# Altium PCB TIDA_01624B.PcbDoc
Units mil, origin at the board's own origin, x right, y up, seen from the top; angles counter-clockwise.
Board outline 1500.72 x 1500.72 mil, 2 copper layers (Top Layer, Bottom Layer), stack 9.4 mil thick; 37 components, 24 nets, 117 pads, 36 vias.
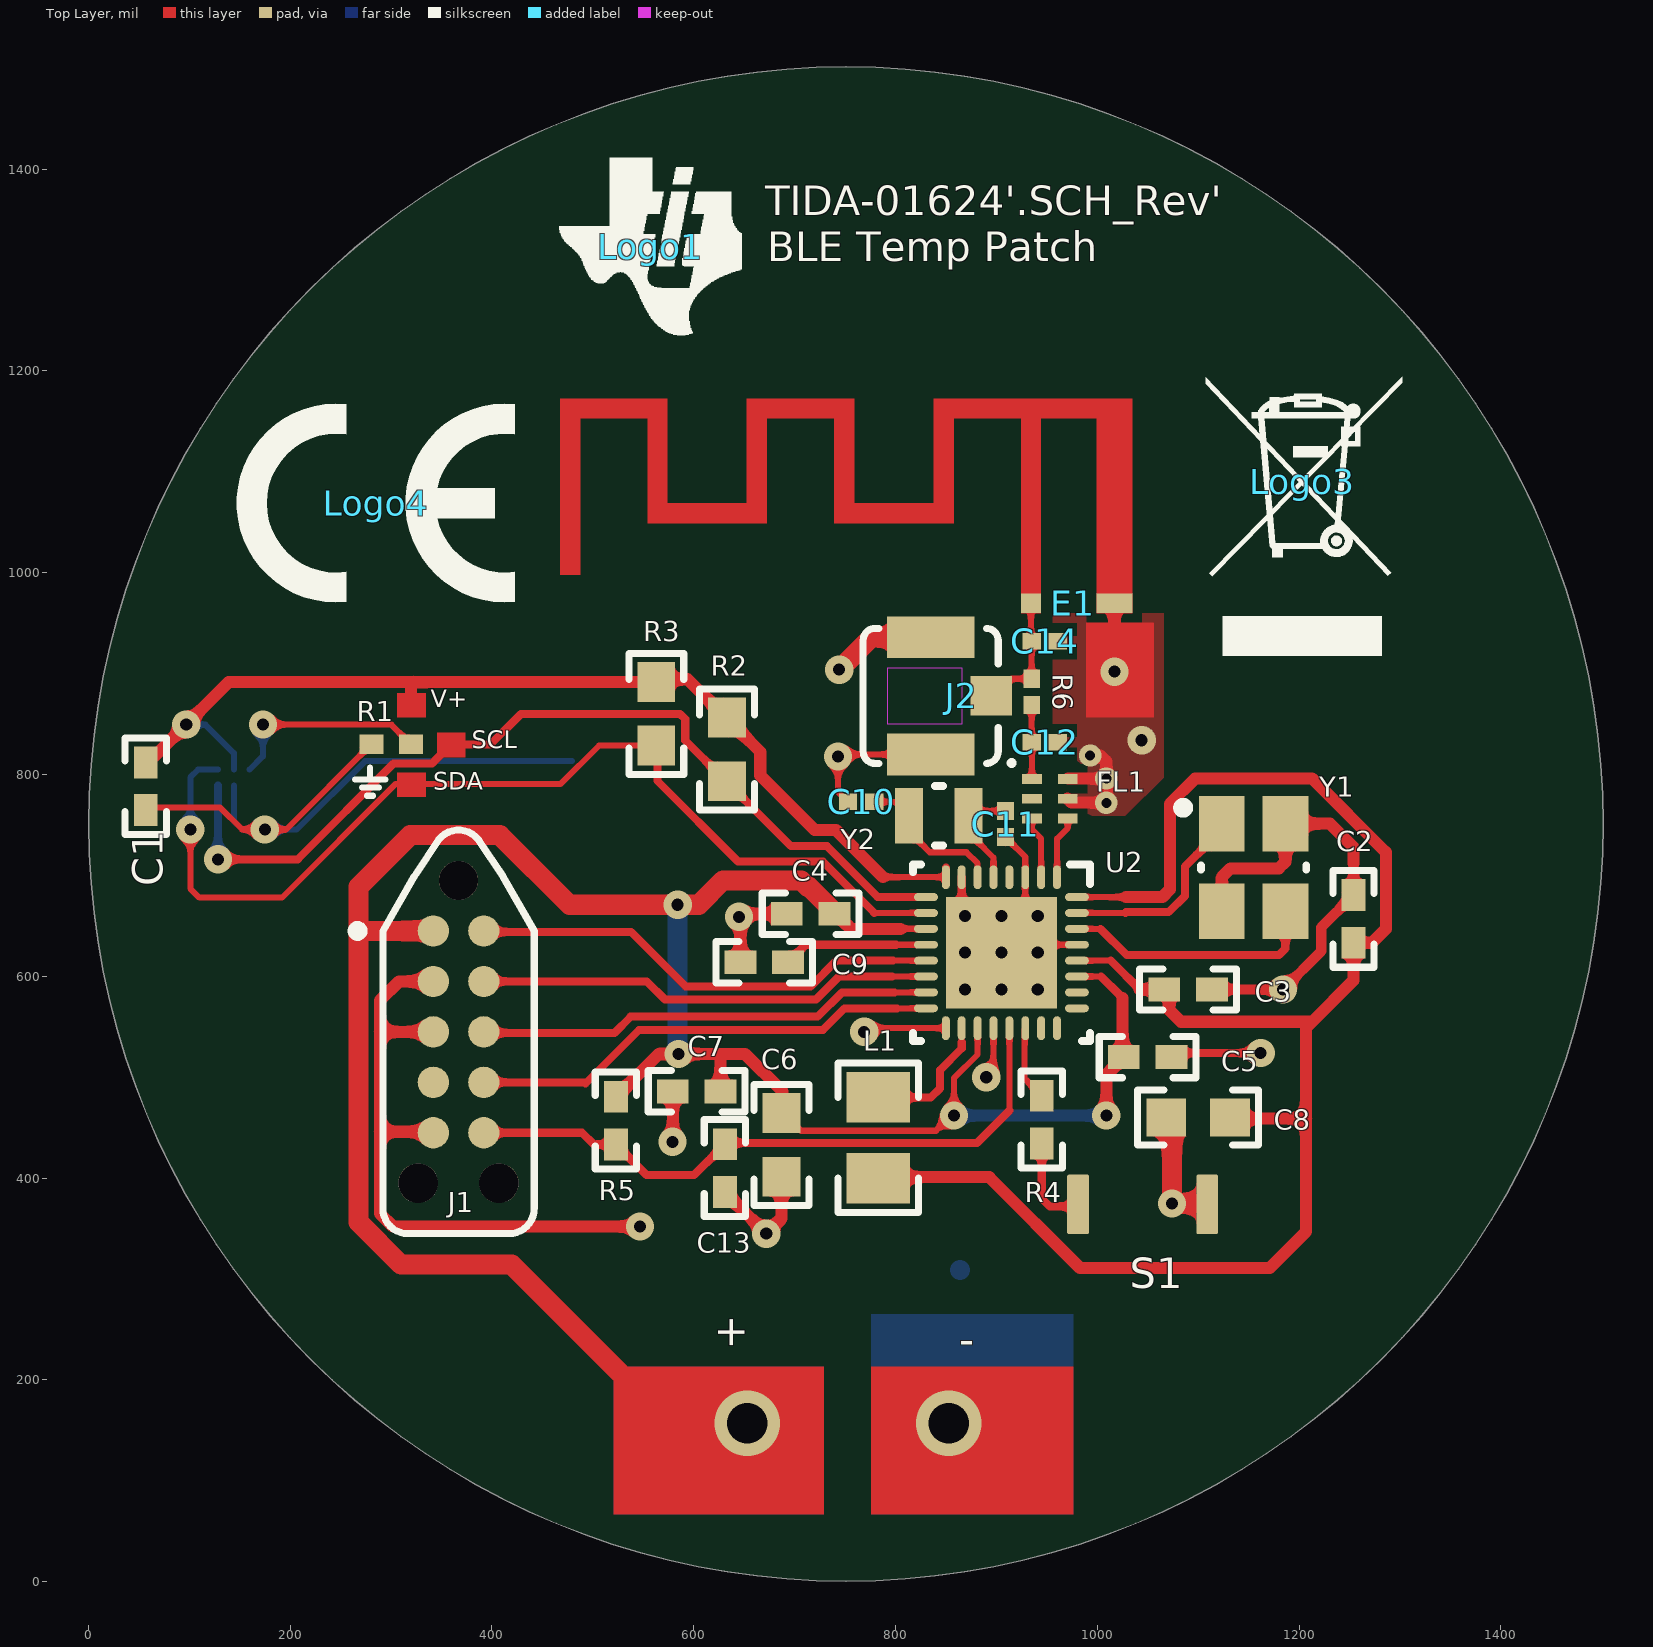
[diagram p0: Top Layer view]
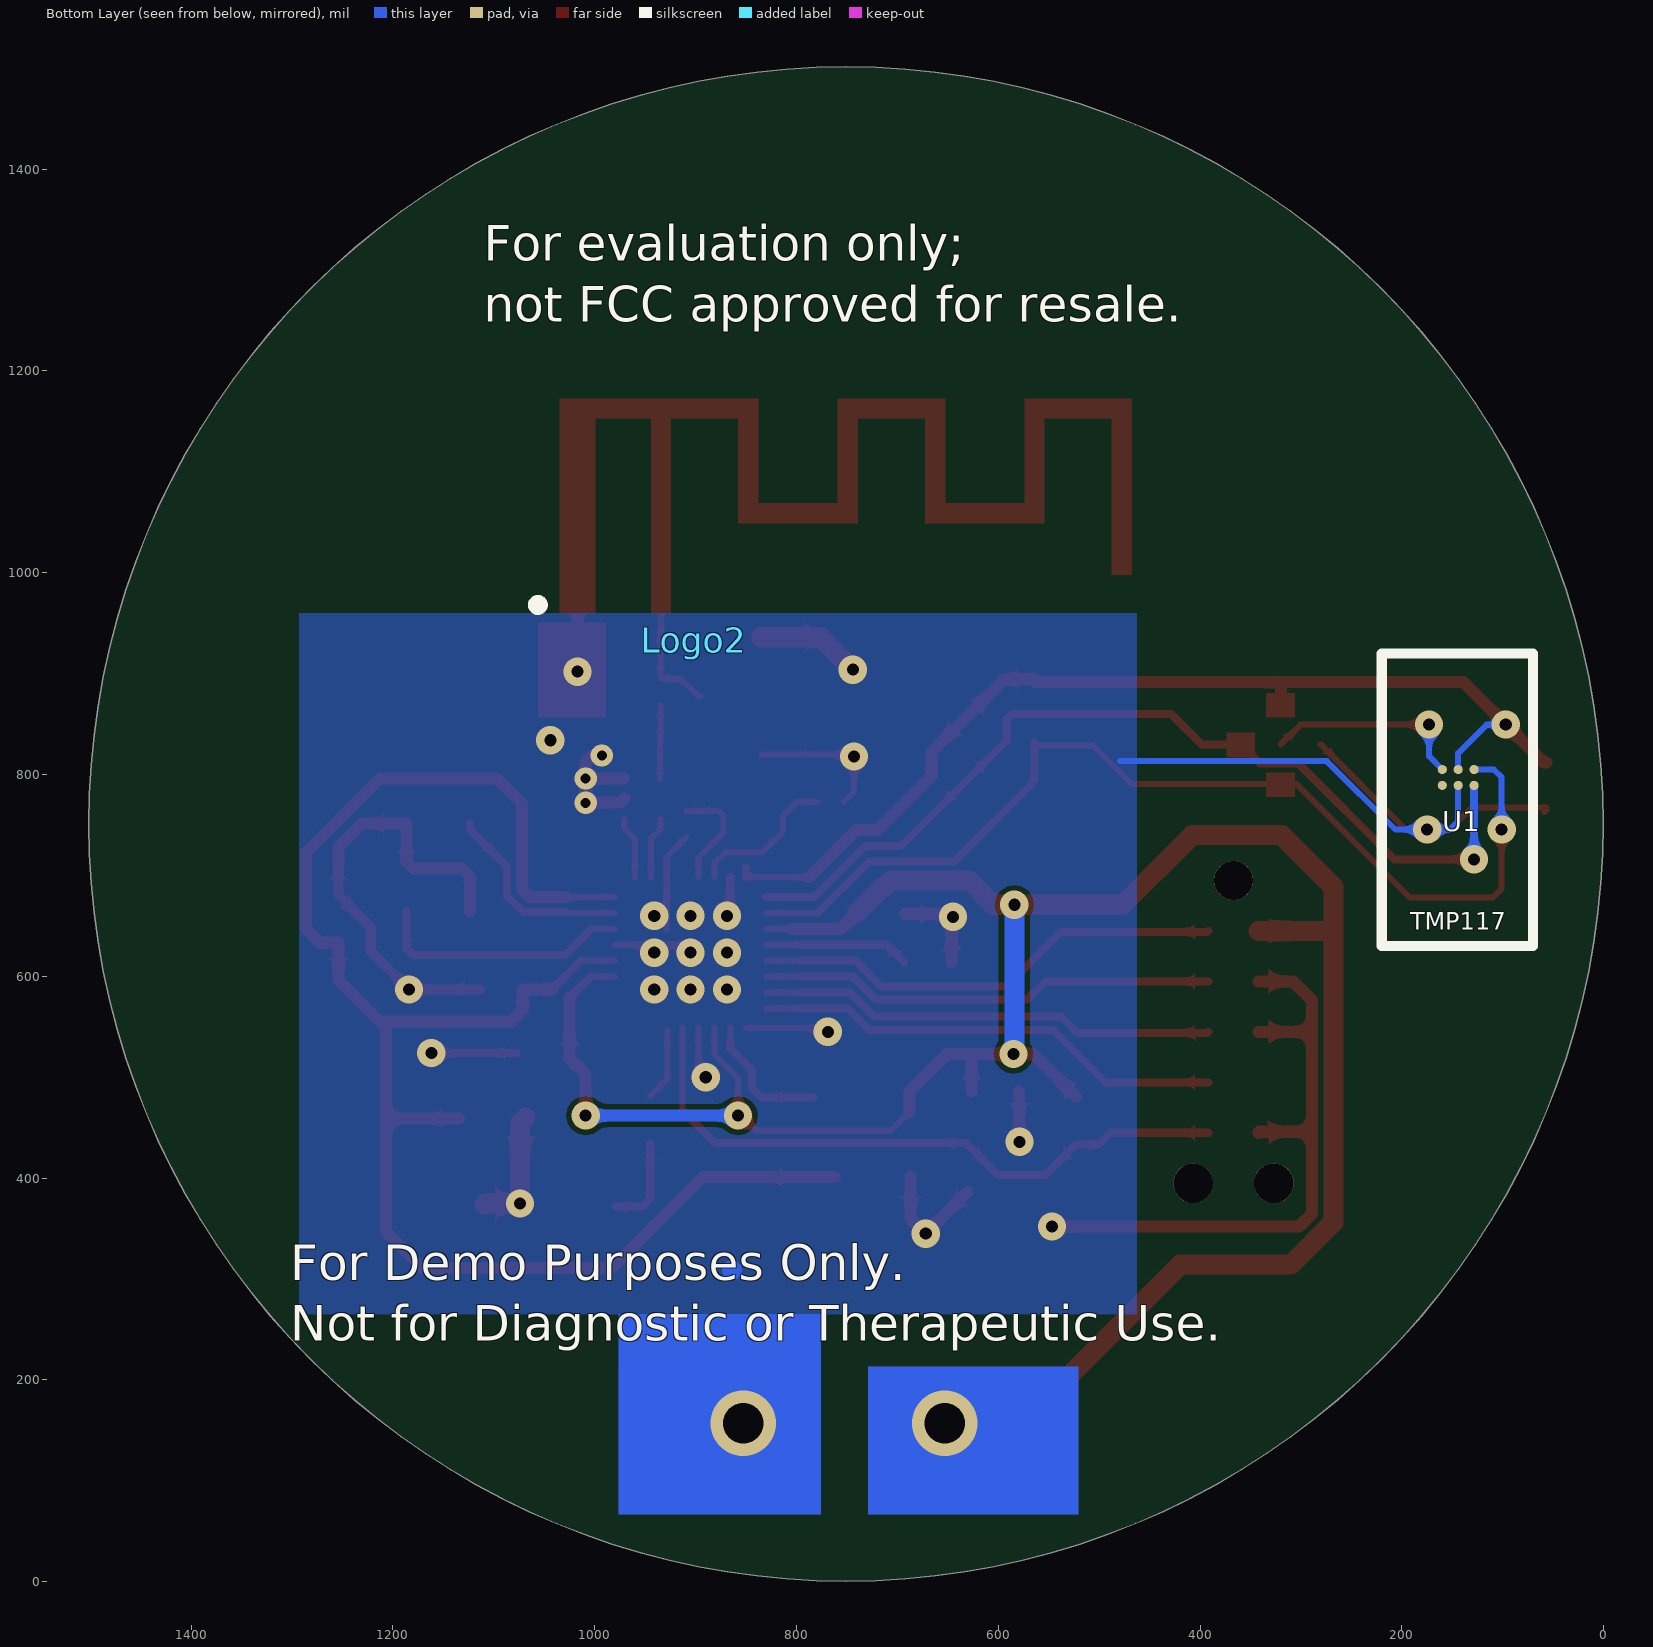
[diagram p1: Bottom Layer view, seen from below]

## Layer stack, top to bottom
Top Solder: solder mask 1, Polymide, Dk 3.3
Top Layer: signal copper 0.7
Stiffener: dielectric 5, Polyimide, Dk 4.2
Flex Substrate: core 3, Polymide, Dk 3.3
Bottom Layer: signal copper 0.7
Bottom Solder: solder mask 1, Polyimide, Dk 3.3

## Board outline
751,0.64 cw(c751,751) 0.64,751 cw(c751,751) 751,1501.36 cw(c751,751) 1501.36,751 cw(c751,751)
board region "Layer Stack Region 1": 220,920 19.55,920 19.85,921.48 32.56,968.94 48.36,1015.46 67.16,1060.85 88.89,1104.91 113.45,1147.45 140.74,1188.3 170.65,1227.28 203.04,1264.22 220,1281.17
board region "Layer Stack Region 1": 220,629.99 10.09,629.99 3.85,677.41 0.64,726.44 0.64,751 0.64,775.56 3.85,824.59 10.26,873.3 19.55,920 220,920
board region "Layer Stack Region 1": 220,220.83 203.04,237.78 170.65,274.72 140.74,313.7 113.45,354.55 88.89,397.09 67.16,441.15 48.36,486.54 32.56,533.06 19.85,580.52 10.26,628.7 10.09,629.99 220,629.99
board region "Layer Stack Region 1": 220,1281.17 237.78,1298.96 274.72,1331.35 313.7,1361.26 354.55,1388.55 397.09,1413.11 441.15,1434.84 486.54,1453.64 533.06,1469.44 580.52,1482.15 628.7,1491.74 677.41,1498.15 726.44,1501.36 751,1501.36 775.56,1501.36 824.59,1498.15 873.3,1491.74 921.48,1482.15 968.94,1469.44 1015.46,1453.64 1060.85,1434.84 1104.91,1413.11 1147.45,1388.55 1188.3,1361.26 1227.28,1331.35 1264.22,1298.96 1298.96,1264.22 1331.35,1227.28 1361.26,1188.3 1388.55,1147.45 1413.11,1104.91 1434.84,1060.85 1453.64,1015.46 1469.44,968.94 1482.15,921.48 1482.45,920 220,920
board region "Layer Stack Region 1": 220,920 1482.45,920 1491.74,873.3 1498.15,824.59 1501.36,775.56 1501.36,751 1501.36,726.44 1498.15,677.41 1491.91,630 220,629.99
board region "Layer Stack Region 1": 220,629.99 1491.91,630 1491.74,628.7 1482.15,580.52 1469.44,533.06 1453.64,486.54 1434.84,441.15 1413.11,397.09 1388.55,354.55 1361.26,313.7 1331.35,274.72 1298.96,237.78 1264.22,203.04 1227.28,170.65 1188.3,140.74 1147.45,113.45 1104.91,88.89 1060.85,67.16 1015.46,48.36 968.94,32.56 921.48,19.85 873.3,10.26 824.59,3.85 775.56,0.64 751,0.64 726.44,0.64 677.41,3.85 628.7,10.26 580.52,19.85 533.06,32.56 486.54,48.36 441.15,67.16 397.09,88.89 354.55,113.45 313.7,140.74 274.72,170.65 237.78,203.04 220,220.83

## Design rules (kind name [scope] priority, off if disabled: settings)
AcuteAngle [All] p1: minimum=4.50000000000000E+0001 checktracksonly=FALSE
AssemblyTestPointUsage [All] p1: valid=2
BoardOutlineClearance BoardOutlineClearance_MountingHoles [OnCopper and InComponentClass('Mounting Holes')] p1 off: gap=40 ignorepadtopadclearanceinfootprint=FALSE
BoardOutlineClearance BoardOutlineClearance_Poly [OnCopper and IsPoly] p2: gap=25 ignorepadtopadclearanceinfootprint=FALSE
BoardOutlineClearance [OnCopper and Not InComponentClass('Logo') and not InComponentClass('FiducialMark') and not InRegion(1000,500,4000,800) and not InPoly] p3 off: gap=40 ignorepadtopadclearanceinfootprint=FALSE
Clearance Clearance_2 [InNamedPolygon('GND_L01_P002') vs InComponent('E1')] p1: gap=0 ignorepadtopadclearanceinfootprint=FALSE
Clearance Clearance_Keepouts [((IsTrack Or IsArc) And Not InPoly) And IsFree and IsKeepOut vs ((IsTrack Or IsArc) And Not InPoly) And IsFree and IsKeepOut] p2: gap=0 ignorepadtopadclearanceinfootprint=FALSE
Clearance Clearance_Poly [InPolygon] p3 off: gap=25 ignorepadtopadclearanceinfootprint=FALSE except(0: Arc-Hole Track-Hole SMDPad-Hole THPad-Hole Via-Hole Fill-Hole Poly-Hole Region-Hole Text-Hole)
Clearance [All] p4: gap=5 ignorepadtopadclearanceinfootprint=FALSE
ComponentClearance ComponentClearance_MountingHoles_FiducialMarks [InComponentClass('Mounting Holes') vs InComponentClass('FiducialMark')] p1: gap=50 collisioncheckmode=3 verticalgap=10 showdistances=FALSE
ComponentClearance ComponentClearance_Shunt [InComponentClass('Header') vs InComponentClass('Shunt')] p2: gap=0 collisioncheckmode=3 verticalgap=0 showdistances=FALSE
ComponentClearance ComponentClearance_Logo [InComponentClass('Logo')] p3: gap=0 collisioncheckmode=3 verticalgap=0 showdistances=FALSE
ComponentClearance ComponentClearance_ScrewToNut [(HasFootprint('NY PMS 440 0025 PH')) vs (HasFootprint('Keystone_1902C'))] p4: gap=5 collisioncheckmode=3 verticalgap=10 showdistances=FALSE
ComponentClearance ComponentClearance_MountingHoles [InComponentClass('Mounting Holes')] p5: gap=250 collisioncheckmode=3 verticalgap=100000 showdistances=FALSE
ComponentClearance ComponentClearance_SmallPassives [HasFootprint('0201*') or HasFootprint('0402*') or HasFootprint('0508') or HasFootprint('0603*') or HasFootprint('0612') or HasFootprint('0805*') or HasFootprint('0815*') or HasFootprint('0830*') or HasFootprint('1206*') or HasFootprint('1210*') or HasFootprint('1808*') or HasFootprint('1812*') or HasFootprint('1825*') or HasFootprint('2010*') or HasFootprint('2220*') or HasFootprint('2225*') or HasFootprint('2512*') or HasFootprint('2728*') or HasFootprint('3518*') vs HasFootprint('0201*') or HasFootprint('0402*') or HasFootprint('0508') or HasFootprint('0603*') or HasFootprint('0612') or HasFootprint('0805*') or HasFootprint('0815*') or HasFootprint('0830*') or HasFootprint('1206*') or HasFootprint('1210*') or HasFootprint('1808*') or HasFootprint('1812*') or HasFootprint('1825*') or HasFootprint('2010*') or HasFootprint('2220*') or HasFootprint('2225*') or HasFootprint('2512*') or HasFootprint('2728*') or HasFootprint('3518*')] p6: gap=14.96 collisioncheckmode=3 verticalgap=10 showdistances=FALSE
ComponentClearance ComponentClearance_THtoSMT [IsThruComponent vs IsSMTComponent] p7: gap=40 collisioncheckmode=3 verticalgap=30 showdistances=FALSE
ComponentClearance ComponentClearance_THtoTH [IsThruComponent vs IsThruComponent] p8: gap=15 collisioncheckmode=3 verticalgap=30 showdistances=FALSE
ComponentClearance [All] p9: gap=15 collisioncheckmode=3 verticalgap=10 showdistances=FALSE
DiffPairsRouting [All] p1: maxlimit=100 minlimit=10 mostfreqgap=10 toplayer_minwidth=15 toplayer_maxwidth=15 toplayer_prefwidth=15 bottomlayer_minwidth=15 bottomlayer_maxwidth=15 bottomlayer_prefwidth=15 maxuncoupledlength=1000
FabricationTestPointUsage TestPointUsage [All] p1: valid=2 allowmultiple=FALSE
FabricationTestpoint Testpoint [All] p1: side=3 testpointundercomponent=TRUE minsize=40 maxsize=100 preferedsize=60 minholesize=0 maxholesize=40 preferedholesize=32 testpointgrid=1 allowsidetop=TRUE allowsidebottom=TRUE usegrid=TRUE gridtolerance=0.01
FanoutControl Fanout_LCC [IsLCC] p1: bgadir=Out bgaviamode=Centered fanoutstyle=Auto fanoutdirection=Alternating viagrid=1 // Fanout_LCC (Default Rule)
FanoutControl Fanout_BGA [IsBGA] p2: bgadir=Out bgaviamode=Centered fanoutstyle=Auto fanoutdirection=Alternating viagrid=1 // Fanout_BGA (Default Rule)
FanoutControl Fanout_Default [All] p4: bgadir=Out bgaviamode=Centered fanoutstyle=Auto fanoutdirection=Alternating viagrid=1 // Fanout_Default (Default Rule)
FanoutControl Fanout_Small [(CompPinCount < 5)] p5: bgadir=Out bgaviamode=Centered fanoutstyle=Auto fanoutdirection=OutThenIn viagrid=1 // Fanout_Small (Default Rule)
HoleSize [All] p1: absolutevalues=TRUE maxlimit=251 minlimit=7.87 maxpercent=80.000 minpercent=20.000
MinimumAnnularRing MinimumAnnularRing_ThermalPadVias [IsVia and InAnyComponent] p1: minimumring=5.91
MinimumAnnularRing [All] p2: minimumring=5
MinimumSolderMaskSliver MinimumSolderMaskSliver_Logo [InComponentClass('Logo') vs InComponentClass('Logo')] p1: minsoldermaskwidth=0.7
MinimumSolderMaskSliver [All] p2: minsoldermaskwidth=2
PlaneConnect [All] p1: planeconnectstyle=Relief reliefexpansion=10 reliefentries=4 reliefconductorwidth=10 reliefairgap=10
PolygonConnect [All] p1: thpad.connectstyle=Relief thpad.reliefconductorwidth=10 thpad.reliefentries=4 thpad.polygonreliefangle="90 Angle" thpad.airgapwidth=10 smdpad.connectstyle=Relief smdpad.reliefconductorwidth=10 smdpad.reliefentries=4 smdpad.polygonreliefangle="90 Angle" smdpad.airgapwidth=10 via.connectstyle=Direct via.reliefconductorwidth=10 via.reliefentries=4 via.polygonreliefangle="90 Angle" via.airgapwidth=10
RoutingVias ThermalPadVias [IsVia and InAnyComponent] p1: holewidth=7.87 width=19.68 viastyle="Through Hole" minholewidth=7.87 minwidth=19.68 maxholewidth=12.99 maxwidth=23.62
RoutingVias [All] p2: holewidth=12 width=28 viastyle="Through Hole" minholewidth=7.9 minwidth=21.9 maxholewidth=40 maxwidth=65
ShortCircuit NoNet [IsComponentVia and not InAnyNet vs IsComponentPad and not InAnyNet] p1: allowed=TRUE
ShortCircuit [All] p2: allowed=FALSE
SilkToBoardRegionClearance [Not ((IsComment or IsDesignator) And (Hide <> 'False')) and not InRegion(1000,500,4000,800)] p1:
SilkToSilkClearance SilkToSilkClearance_Pb-FreeLogo [HasFootprint('FCC_disclaimer') vs HasFootprint('TI_Symbol_Overlay_Small')] p1: silktosilkclearance=0
SilkToSilkClearance SilkToSilkClearance_Pb-FreeLogo_1 [(HasFootprint('Pb-Free_Overlay_Medium') OR HasFootprint('Pb-Free_Overlay_Small')) vs (HasFootprint('Pb-Free_Overlay_Medium') OR HasFootprint('Pb-Free_Overlay_Small'))] p2: silktosilkclearance=0
SilkToSilkClearance [All] p3: silktosilkclearance=4
SilkToSolderMaskClearance "Silk to Solder Mask Opening" [All] p1: minsilkscreentomaskgap=1.5 clearancetoexposedcopper=FALSE
SolderMaskExpansion [All] p1: expansion=1.97
Width [All] p1: maxlimit=20 minlimit=4 preferedwidth=8 checkconnectedcopper=TRUE
14 further rules are at their usual default settings.

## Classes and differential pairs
component class AssemblyNote: ZZ1 ZZ2 ZZ3
component class Logo: Logo1

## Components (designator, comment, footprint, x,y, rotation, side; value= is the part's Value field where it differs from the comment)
C1 "GRM155R71E104KE14D" 0402 57,788.38 r270 top value=0.1uF
C2 "GRM155R71E104KE14D" 0402 1254,657 r270 top value=0.1uF
C3 "GRM155R71E104KE14D" 0402 1090,587 r180 top value=0.1uF
C4 "GRM155R71E104KE14D" 0402 716,662 r0 top value=0.1uF
C5 "GRM155R71E104KE14D" 0402 1050,520 r180 top value=0.1uF
C6 "C1608X5R1E106M080AC" 0603 687,433 r270 top value=10uF
C7 "GRM155R71E104KE14D" 0402 603,486 r180 top value=0.1uF
C8 "C1608X5R1E106M080AC" 0603 1100,460 r180 top value=10uF
C9 "GRM152R60J105ME15D" 0402 670,614 r0 top value=1uF
C10 "Capacitor" 0201 766,773 r180 top value=12pF
C11 "Capacitor" 0201 909,751 r270 top value=12pF
C12 "DNP" 0201_033 948,832 r0 top
C13 "GRM155R71E104KE14D" 0402 631,410 r270 top value=0.1uF
C14 "DNP" 0201_033 948,932 r0 top
E1 "ANTENNA_IIFA" ANTENNA_IIFA 1017,960 r180 top net-tie
FL1 "2450BM14G0011" Johanson_2450BM14G0011 953,776 r0 top
J1 "DNP - Nothing to buy or mount" Tag_TC2050-NL 367,545 r0 top
J2 "U.FL-R-SMT-1(01)" CONN_UFL-R-SMT-1 834.96,878 r180 top
L1 "CKS2125100M-T" 0805_HV 783,440 r270 top value=10uH
Logo1 "Texas Instruments" TI_Symbol_Overlay_Small 557,1323 r0 top
Logo2 "FCC disclaimer" FCC_disclaimer 901.89,933.12 r180 bottom
Logo3 "WEEE logo" WEEE_Minimum 1203,1090 r0 top
Logo4 "CE Mark" CE_Mark_5mm 285,1069 r0 top
R1 "RC0402JR-070RL" 0402L 300.28,830 r180 top value=0
R2 "RC0603FR-076K98L" 0603 633,825 r90 top value=6.98k
R3 "RC0603FR-076K98L" 0603 563,860.19 r90 top value=6.98k
R4 "ERJ-2RKF2401X" 0402 945,458 r270 top value=2.40k
R5 "ERJ-2RKF1003X" 0402 523,457 r90 top value=100k
R6 "CRCW02010000Z0ED" 0201 935,882 r90 top value=0
S1 "TL3780AF330QG" SW_TL3780 1045,374 r0 top
U1 "TMP117AIYBGR" YBG0006AJAP 144.25,797.13 r270 bottom
U2 "CC2640R2FRSMR" RSM0032B_NV 905.05,623.47 r270 top
Y1 "TSX-3225 24.0000MF15X-AC3" EPSON_TSX-3225 1155,708 r0 top
Y2 "CM2012H32768DZFT" CM2012H 843,759 r0 top
ZZ1 "These assemblies are ESD sensitive, ESD precautions shall be observed." AssemblyNote -1004,2178 r0 top
ZZ2 "These assemblies must be clean and free from flux and all contaminants. Use of no clean flux is not acceptable." AssemblyNote -1005,2064 r0 top
ZZ3 "These assemblies must comply with workmanship standards IPC-A-610 Class 2, unless otherwise specified." AssemblyNote -1007,1949 r0 top

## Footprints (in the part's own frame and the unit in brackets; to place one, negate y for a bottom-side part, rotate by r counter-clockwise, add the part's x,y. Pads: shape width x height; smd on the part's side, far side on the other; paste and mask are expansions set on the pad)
0201 [mm] "Data from Kemet datasheet CC101_COM dated 7/28/11"
  rect 0.46x0.42 smd mask+0.048: 1(-0.33,0) 2(0.33,0)
  body extent -0.31,-0.16 0.31,0.16, height 0.26
0201_033 [mm] "SMD, 2-Leads, Height 0.33mm"
  rect 0.46x0.42 smd mask+0.048: 1(-0.33,0) 2(0.33,0)
  body extent -0.31,-0.16 0.31,0.16, height 0.33
0402 [mm] "0402 from SM-752 data"
  rect 0.8x0.6 smd: 1(-0.6,0) 2(0.6,0)
  silkscreen extent -1.22,-0.52 1.22,0.52, body extent -0.55,-0.3 0.55,0.3, height 0.6
0402L [mm] "0402 from SM-752 data"
  rect 0.6x0.5 smd: 1(-0.5,0) 2(0.5,0)
  body extent -0.55,-0.3 0.55,0.3, height 0.6
0603 [mm] "0603 from SM-752 data"
  rect 1x0.95 smd: 1(-0.8,0) 2(0.8,0)
  silkscreen extent -1.52,-0.69 1.52,0.69, body extent -0.87,-0.47 0.87,0.47, height 1
0805_HV [mil] "0805 with 30mil clearance between pads"
  rect 50x63 smd: 1(-40,0) 2(40,0)
  silkscreen extent -74,-40 74,40, body extent -43,-29 43,29, height 57
ANTENNA_IIFA [mm] "PCB Antenna, 2-Leads"
  rect 0.9x0.5 smd paste-1 mask-1: 1(0,-0.25)
  rect 0.5x0.5 smd paste-1 mask-1: 2(2.1,-0.25)
  Top Layer region: -0.45,0 -0.45,-5.4 4.55,-5.4 4.55,-2.76 6.55,-2.76 6.55,-5.4 9.25,-5.4 9.25,-2.76 11.25,-2.76 11.25,-5.4 13.95,-5.4 13.95,-0.96 13.45,-0.96 13.45,-4.9 11.75,-4.9 11.75,-2.26 8.75,-2.26 8.75,-4.9 7.05,-4.9 7.05,-2.26 4.05,-2.26 4.05,-4.9 2.35,-4.9 2.35,0 1.85,0 1.85,-4.9 0.45,-4.9 0.45,0
AssemblyNote [mil] "Assembly Note"
CE_Mark_5mm [mil] "Minimum text height for CE Mark"
  silkscreen extent -138,-98 138,98
CM2012H [mm] "SMD, 2-Leads, Body 2.05x1.2mm"
  rect 0.7x1.4 smd: 1(-0.75,0) 2(0.75,0)
  silkscreen extent -0.1,-0.75 0.1,0.75, body extent -1.07,-0.65 1.07,0.65, height 0.6
CONN_UFL-R-SMT-1 [mm] "Hirose recommended land pattern http://www.hirose.co.jp/cataloge_hp/e32119372.pdf 2009.2"
  rect 1.05x1 smd paste-0.1 mask-0.1: 1(-1.525,0)
  rect 2x0.9 on Top Paste: 2(0,1.5) 3(0,-1.5)
  rect 2x0.9 on Top Solder: 2(0,1.5) 3(0,-1.5)
  rect 2.2x1.05 smd paste-2 mask-2: 2(0,1.475) 3(0,-1.475)
  Top Layer keep-out region: -0.8,-0.7 1.1,-0.7 1.1,0.7 -0.8,0.7
  silkscreen extent -1.7,-1.7 1.7,1.7, body extent -1.55,-1.5 1.55,1.5, height 1.27
EPSON_TSX-3225 [mm] "SMD, 4-Leads, Body 2.65x3.35mm, Height 0.6mm"
  rect 1.15x1.4 smd: 1(-0.8,1.1) 2(-0.8,-1.1) 3(0.8,-1.1) 4(0.8,1.1)
  silkscreen extent -1.9,-0.05 1.33,1.62, body extent -1.33,-1.68 1.33,1.68, height 0.61
FCC_disclaimer [mil]
Johanson_2450BM14G0011 [mm] "SMD, 6-Leads, Body 1.6x0.8mm, Pitch 0.5mm"
  rect 0.5x0.25 smd: 1(-0.45,0.5) 2(-0.45,0) 3(-0.45,-0.5) 4(0.45,-0.5) 5(0.45,0) 6(0.45,0.5)
  silkscreen extent -1.02,0.84 -0.9,0.96, body extent -0.45,-0.85 0.45,0.85, height 0.71
RSM0032B_NV [mm] "QFN, 32-Leads, Body 4x4mm, Pitch 0.4mm, Thermal Pad 2.8x2.8mm, TI Recommended"
  oval 0.6x0.2 smd: 1(-1.9,1.4) 2(-1.9,1) 3(-1.9,0.6) 4(-1.9,0.2) 5(-1.9,-0.2) 6(-1.9,-0.6) 7(-1.9,-1) 8(-1.9,-1.4) 17(1.9,-1.4) 18(1.9,-1) 19(1.9,-0.6) 20(1.9,-0.2) 21(1.9,0.2) 22(1.9,0.6) 23(1.9,1) 24(1.9,1.4)
  oval 0.2x0.6 smd: 9(-1.4,-1.9) 10(-1,-1.9) 11(-0.6,-1.9) 12(-0.2,-1.9) 13(0.2,-1.9) 14(0.6,-1.9) 15(1,-1.9) 16(1.4,-1.9) 25(1.4,1.9) 26(1,1.9) 27(0.6,1.9) 28(0.2,1.9) 29(-0.2,1.9) 30(-0.6,1.9) 31(-1,1.9) 32(-1.4,1.9)
  rect 2.8x2.8 smd paste-1.4: 33(0,0)
  silkscreen extent -2.23,-2.23 2.23,2.23, body extent -2.07,-2.07 2.08,2.08, height 1.01
SW_TL3780 [mm] "SMD, 2-Leads, Body 3x2mm"
  rrect18% 0.55x1.5 smd: 1(-1.625,0) 2(1.625,0)
  body extent -1.63,-1.12 1.63,1.12, height 0.7
Tag_TC2050-NL [mil] "Footprint for Tag-Connect TC2050 No-Legs cables"
  round 31 smd paste-15.75: 1(-25,100) 2(-25,50) 3(-25,0) 4(-25,-50) 5(-25,-100) 6(25,-100) 7(25,-50) 8(25,0) 9(25,50) 10(25,100)
  round 39 hole 39 unplated: MH1(0,150) MH2(-40,-150) MH3(40,-150)
  silkscreen extent -105,-200 75,200
TI_Symbol_Overlay_Small [mil]
  silkscreen extent -90,-88 91,88
WEEE_Minimum [mil] "WEEElie bin"
  silkscreen extent -95,-172 99,104
YBG0006AJAP [mm] "DSBGA-6"
  round 0.23 smd paste-0.23 mask+0.032: A1(-0.2,0.4) A2(0.2,0.4) B1(-0.2,0) B2(0.2,0) C1(-0.2,-0.4) C2(0.2,-0.4)
  body extent -0.61,-0.81 0.62,0.82, height 0.5

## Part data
C1 C2 C3 C4 C5 C7 C13: library part CMP-0006659-2, "CAP, CERM, 0.1 uF, 25 V, +/- 10%, X7R, 0402", Cap_Case=0402, Manufacturer=MuRata, Supplier Part Number 1=490-10698-1-ND, TempCo=X7R, Tolerance_%=10%, Value1=Unknown, Value2=25V, ValueDisplayed=0.1uF
C6 C8: library part CMP-0007007-5, "CAP, CERM, 10 uF, 25 V, +/- 20%, X5R, 0603", Cap_Case=0603, Manufacturer=TDK, Supplier Part Number 1=445-9015-1-ND, TempCo=X5R, Tolerance_%=20%, Value1="0.004639 ohm", Value2=25V, ValueDisplayed=10uF
C9: library part CMP-0006372-2, "CAP, CERM, 1 uF, 6.3 V, +/- 20%, X5R, 0402", Cap_Case=0402, Manufacturer=MuRata, Supplier Part Number 1=490-10006-1-ND, TempCo=X5R, Tolerance_%=20%, Value1=Unknown, Value2=6.3V, ValueDisplayed=1uF
C10 C11: library part CMP-0009664-3, "CAP, CERM, 12 pF, 50 V, +/- 5%, C0G/NP0, 0201", Cap_Case=0201, Manufacturer=MuRata, PartNumber=GRM0335C1H120JA01D, Supplier Part Number 1=490-6114-1-ND, TempCo=C0G/NP0, Tolerance_%=5%, Value1=Unknown, Value2=50V, ValueDisplayed=12pF
C12 C14: library part CMP-0009654-3, "CAP, CERM, 470 pF, 50 V, +/- 10%, X7R, AEC-Q200 Grade 1, 0201"
E1: library part CMP-0001736-1, "PCB Antenna.  There is nothing to buy or mount.", Manufacturer=N/A
FL1: library part CMP-0001890-2, "2.4GHz Impedance Matched Balun + embedded FCC/ETSI Band Pass Filter, SMD", Manufacturer="Johanson Technology"
J1: library part CMP-0075101-1, "Footprint for Tag-Connect TC2050 No-Legs cables", Manufacturer=Tag-Connect, PartNumber=TC2050-IDC-NL-FP
J2: library part CMP-0075320-1, "Receptacle, Ultra Miniature Coaxial, Male Pin, 50 ohm, SMT", Color=Beige, Manufacturer="Hirose Electric Co. Ltd.", Supplier Part Number 1=H122041-ND
L1: library part CMP-0059606-1, "Inductor, Multilayer, Ferrite, 10 uH, 0.11 A, 0.52 ohm, SMD", Manufacturer="Taiyo Yuden", Supplier Part Number 1=587-2608-1-ND, Value1="0.52 ohm", Value2=0.11A, ValueDisplayed=10uH
Logo1: library part CMP-0074838-1, "Texas Instrument Corporate Signature"
Logo2: library part CMP-0074847-1, "FCC_disclaimer"
Logo3: library part CMP-0074769-1
Logo4: library part CMP-0074844-1
R1: library part CMP-0027004-2, "RES, 0, 5%, 0.063 W, 0402", Manufacturer="Yageo America", Power_W=63mW, Supplier Part Number 1=311-0.0JRCT-ND, TempCo="200 ppm/C", Tolerance_%=5%, Value2=0.063W, Value_Code=0000, ValueDisplayed=0
R2 R3: library part CMP-0023254-3, "RES, 6.98 k, 1%, 0.1 W, 0603", Manufacturer="Yageo America", Power_W=100mW, Supplier Part Number 1=311-6.98KHRCT-ND, TempCo="200 ppm/C", Tolerance_%=1%, Value2=0.1W, Value_Code=6k98, ValueDisplayed=6.98k
R4: library part CMP-0026685-1, "RES, 2.40 k, 1%, 0.1 W, AEC-Q200 Grade 0, 0402", Manufacturer=Panasonic, Power_W=100mW, Supplier Part Number 1=P2.40KLCT-ND, TempCo="100 ppm/C", Tolerance_%=1%, Value2=0.1W, Value_Code=2k40, ValueDisplayed=2.40k
R5: library part CMP-0026659-1, "RES, 100 k, 1%, 0.1 W, 0402", Manufacturer=Panasonic, Power_W=100mW, TempCo="100 ppm/C", Tolerance_%=1%, Value2=0.1W, Value_Code=100k
R6: library part CMP-0027008-4, "RES, 0, 5%, 0.05 W, 0201", Manufacturer=Vishay-Dale, Power_W=50mW, Supplier Part Number 1=72M6743, TempCo=ppm/C, Tolerance_%=5%, Value2=0.05W, Value_Code=0000, ValueDisplayed=0
S1: library part CMP-0084104-1, "Switch, SPST-NO, 0.05 A, 12 VDC, SMT", CurrentRating_mA=50A, Manufacturer=E-Switch
U1: library part CMP-0860099-1, "±0.1°C accurate digital temperature sensor with integrated NV memory, YBG0006AJAP (DSBGA-6)", Alternate Manufacturer="Texas Instruments", Alternate PartNumber=TMP117AIYBGT, Operating Temperature Range="-55 to 150,0 to 85 C", Rating=Catalog
U2: library part CMP-0076686-1, "SimpleLink(TM) Bluetooth(R) low energy Wireless MCU, RSM0032B (VQFN-32)", Alternate Manufacturer="Texas Instruments", Alternate PartNumber=CC2640R2FRSMT
Y1: library part CMP-0079304-1, "Crystal, 24 MHz, 10 ppm, 9 pF, SMD", Frequency_Fixed=24MHz, Frequency Stability="15 ppm", Frequency Tolerance="10 ppm", Load Capacitance="9 pF", Manufacturer=Epson, Supplier Part Number 1=SER3635CT-ND
Y2: library part CMP-0004654-3, "Crystal, 32.768 kHz, SMD", Frequency_Fixed=32.768kHz, Frequency Stability=+/-20ppm, Manufacturer="Citizen Electronics", Supplier Part Number 1=300-8818-1-ND
ZZ1: library part CMP-0077236-1
ZZ2: library part CMP-0077237-1
ZZ3: library part CMP-0077238-1

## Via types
v1: diameter 28, hole 12, Top Layer to Bottom Layer, tented both sides, 21 vias
v2: diameter 28, hole 12, Top Layer to Bottom Layer, tented bottom, 10 vias
v3: diameter 22, hole 10, Top Layer to Bottom Layer, tented both sides, 3 vias
v4: diameter 64.96, hole 40, Top Layer to Bottom Layer, 2 vias

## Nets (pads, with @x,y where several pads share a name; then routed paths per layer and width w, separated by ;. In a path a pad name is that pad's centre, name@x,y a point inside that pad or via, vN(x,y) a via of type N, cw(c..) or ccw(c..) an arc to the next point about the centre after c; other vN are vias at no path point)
DCDC_SW: L1.1 U2.18 | length 133.4
  Top Layer w6: 865.68,534.68 U2.18
  Top Layer w8: L1.1 835,480 844,489 844,507 865.68,528.68 865.68,534.68
GND: C1.2 C2.1 C3.1 C4.1 C5.1 C6.2 C7.2 C8.2 C9.1 C10.2 C11.2 C12.2 C13.2 C14.2 E1.1 FL1.5 FL1.6 J1.2 J1.3 J1.5 J2.2@834.96,819.93 J2.3@834.96,936.07 R1.2 S1.2 U1.B2 U2.3 U2.7 U2.17 U2.20 U2.29 U2.33 Y1.2 Y1.4 | length 2991.7
  Top Layer w6: C1.2@58.76,763 C1.2 57,767.55 130.45,767.55 152.45,745.55 v1(175,745.55) 196.14,745.55 R1.2 ; C10.2 743,783.01 v1(743,818) 744.93,819.93 J2.2@834.96,819.93 ; v1(769,545) 772.67,548.67 U2.17 U2.17@850.06,548.79 ; v1(890,500) 897.18,507.18 U2.20 ; C11.2 928.68,718.33 U2.33@928.68,647.09 ; U2.33@912.93,631.34 U2.29
  Top Layer w8: U2.33@865.68,662.84 U2.7 ; C5.1@1077.62,524 v1(1162,524)
  Top Layer w10: C3.1 v1(1184,587) 1222,625 1222,648.62 C2.1 1254,712
  Top Layer w12: J1.5 341,446 289,446 ; J1.3 289,545 ; J1.2 308,595 289,576 289,545 ; v1(546.75,352) 302,352 289,365 289,446 ; v1@579.38,436.38 C7.2 ; C13.2 631,386 v1(672,345) 687,360 C6.2 ; C9.1 v1@646.38,657.62 ; v1@650.76,662 C4.1 ; FL1.5 974.48,772.24 1008.76,772.24 v3(1009,772) v3(1009,796) ; FL1.6@971.03,796 v3(1009,796) ; v3(993,819) 1003,819 1009,813 v3(1009,796) ; 1017,935 E1.1 ; Y1.2 1123.5,698.5 1132,707 1180,707 1186.5,713.5 Y1.4 1230.69,751.31 1254,728 1254,712 ; 289,446 289,545
  Top Layer w20: v1(744.23,904) 776.3,936.07 J2.3@834.96,936.07 ; C8.2 1074,454.5 v1(1074,375) 1107.98,375 S1.2
  Bottom Layer w6: U1.B2 144.25,753.75 152.45,745.55 v1(175,745.55) 206.55,745.55 274.38,813.38 479.33,813.38
  other v1: 579,436 645,659 1044,834
  other v2: 869,587 905,587 941,587 869.05,623.47 905.05,623.47 941.05,623.47 869,660 905,660 941,660 1017,902
  other v4: 853,157
JTAG_RST: C13.1 J1.6 R5.1 U2.21 | length 644.6
  Top Layer w6: 912.93,466.93 U2.21
  Top Layer w8: J1.6 489.5,445 501.12,433.38 R5.1 553.38,403 600.38,403 C13.1 ; C13.1@632.38,435 881,435 912.93,466.93
JTAG_TCKC: J1.9 U2.14 | length 455.2
  Top Layer w6: 796.85,599.85 U2.14
  Top Layer w8: J1.9 553.5,595 571.5,577 721.38,577 744.23,599.85 796.85,599.85
JTAG_TDI: J1.7 U2.16 | length 469.5
  Top Layer w6: 801.35,568.35 U2.16@830.25,568.35
  Top Layer w8: J1.7 492,495 493,494 546.04,547.04 728.19,547.04 749.5,568.35 801.35,568.35
JTAG_TDO: J1.8 U2.15 | length 455.3
  Top Layer w6: 798.9,584.1 U2.15
  Top Layer w8: J1.8 393,544 521.56,544 537.6,560.04 722.81,560.04 746.87,584.1 798.9,584.1
JTAG_TMSC: J1.10 U2.13 | length 471.6
  Top Layer w6: 797.41,615.59 U2.13
  Top Layer w8: J1.10 393,644 538.12,644 592.12,590 716,590 741.59,615.59 797.41,615.59
NetC9_2: C9.2 U2.12 | length 143.8
  Top Layer w6: 800.66,631.34 U2.12
  Top Layer w8: C9.2 710.96,631.34 800.66,631.34
NetC12_1: C12.1 FL1.1 R6.1 | length 72
  Top Layer w6: C12.1 R6.1 ; FL1.1 C12.1@935.28,830.72
NetC14_1: C14.1 E1.2 J2.1 R6.2 | length 121.6
  Top Layer w6: J2.1 898,878 914.99,894.99 R6.2 C14.1 ; C14.1@934.32,932.68 E1.2
  Top Layer w10: C14.1@934.01,933 C14.1@934.32,932.68
NetR1_1: R1.1 U1.C1 | length 204.9
  Top Layer w6: v1(173.08,849.55) 300.42,849.55 R1.1
  Bottom Layer w6: U1.C1 173.08,818.08 v1(173.08,849.55)
NetR4_2: R4.2 S1.1 | length 91.7
  Top Layer w8: R4.2 945,380 953,372 S1.1@979.02,372
RF_N: FL1.3 U2.2 | length 62.1
  Top Layer w4: FL1.3@935,756.03 FL1.3
  Top Layer w6: FL1.3@935,756.03 935,745.85 944.42,736.42 U2.2
RF_P: FL1.4 U2.1 | length 62.8
  Top Layer w4: 960.17,736.83 960.83,736.83
  Top Layer w6: U2.1 960.17,736.83 ; 960.83,736.83 970.72,746.72 FL1.4
SCL: R2.1 U1.A2 U2.9 | length 922.3
  Top Layer w8: v1(128.5,716) 207.61,716 302.61,811 340.63,811 359.63,830 398.81,830 429,860.19 586.43,860.19 591.7,854.92 591.7,833.8 696.5,729 732,729 782.41,678.59 U2.9
  Bottom Layer w8: v1(128.5,716) U1.A2
SDA: R3.1 U1.A1 U2.10 | length 1026.7
  Top Layer w6: v1(101.15,745.55) 101.15,687 110.15,678 192,678 304.69,790.69 468.18,790.69 506.19,828.69 R3.1 ; 779,663 U2.10@830.09,663
  Top Layer w8: R3.1@564,831.5 564,793.9 643.9,714 728,714 779,663
  Bottom Layer w6: v1(101.15,745.55) 101.15,797.15 109,805 U1.A1
V+: C1.1 R2.2 R3.2 U1.B1 U2.8 | length 1033.7
  Top Layer w6: 787.66,698.34 U2.8 U2.8@850,698.34
  Top Layer w8: U2.8 U2.8 U2.8@849.94,708.06
  Top Layer w12: C1.1 59.53,812 v1(97.08,849.55) 139.22,891.68 321.94,891.68 ; 323.59,872.67 319.92,869 319.92,889.66 321.94,891.68 ; R3.2 321.94,891.68 ; R3.2@564,894.5 594,894.5 666,822.5 666,799 720,745 741,745 787.66,698.34
  Bottom Layer w6: v1(97.08,849.55) 116.04,849.55 144.25,821.33 U1.B1
VCC: C4.2 C5.2 C6.1 C7.1 J1.1 R5.2 U2.11 U2.19 U2.27 | length 2523.6
  Top Layer w6: C6.1@688,465.5 706.5,447 840,447 v1@855,462 ; 804.91,647.09 U2.11 ; v1(858,462) 858,499.11 881.43,522.54 U2.19 ; U2.27 1003.85,599.85
  Top Layer w8: 1003.85,599.85 1025,578.69
  Top Layer w12: R5.2 565.38,523 v1(585,523) 651,523 688,486 C6.1@688,465.5 ; C7.1 626.62,519.62 ; C4.2@739.62,663.53 756.06,647.09 804.91,647.09 ; v1(1009,462) 1009,502.62 C5.2 ; C5.2@1025,521.38 1025,578.69
  Top Layer w20: J1.1 270,645 268,647 ; v4@656,157 577,157 419.7,314.3 310,314.3 268,356.3 268,647 ; C4.2@739.62,663.53 714.34,688.81 712.81,688.81 706.62,695 629,695 605,671 v1(584.15,671) 477,671 408,740 319.13,740 268,688.87 268,647
  Bottom Layer w12: v1(858,462) v1(1009,462)
  Bottom Layer w20: v1@584.15,523.85 v1(584.15,671)
  other v4: 653,157
VDDR: C2.2 C3.2 C8.1 L1.2 U2.28 U2.32 | length 1695.3
  Top Layer w6: U2.28 1013.41,615.59 ; U2.32 1028.41,678.59
  Top Layer w8: 1013.41,615.59 1042,587
  Top Layer w12: L1.2@762,401 893,401 983,311 1171,311 1207,347 1207,459 ; 1028.41,678.59 1064.59,678.59 1072,686 1072,771 1097,796 1213,796 1286,723 1286,647 1272.38,633.38 C2.2 1254,596 1213,555 ; 1042,587 1071.38,587 1071.38,566.62 1083,555 1213,555 ; C8.1@1134.5,459 1207,459 ; 1207,459 1207,551 1209,551 1213,555
WAKE: R4.1 U2.22 | length 72.8
  Top Layer w6: U2.22@928,547.34 928,498.62 R4.1
X24M_N: U2.30 Y1.3 | length 257.2
  Top Layer w6: U2.30@979.95,647 1003.21,647
  Top Layer w8: 1003.21,647 1029.21,621 1180,621 1186.5,627.5 Y1.3
X24M_P: U2.31 Y1.1 | length 200.8
  Top Layer w6: U2.31 1027.84,662.84
  Top Layer w8: 1027.84,662.84 1028.59,663.59 1070.8,663.59 1087,679.79 1087,709 1123.5,745.5 Y1.1
X32K_Q1: C11.1 U2.5 Y2.2 | length 109.5
  Top Layer w6: U2.5 897.18,717.54 872.53,742.2 Y2.2 877.52,763.99 C11.1
X32K_Q2: C10.1 U2.6 Y2.1 | length 150.5
  Top Layer w6: C10.1 799.47,773 Y2.1 813.47,743.53 834,723 870.39,723 881.43,711.96 U2.6
pads on no net: FL1.2 J1.4 J1.MH1 J1.MH2 J1.MH3 J2.2@834.96,818.94 J2.3@834.96,937.06 U1.C2 U2.4 U2.23 U2.24 U2.25 U2.26

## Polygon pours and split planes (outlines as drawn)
GND on Bottom Layer "Bottom Layer-GND" (solid, pour order 2): 463,960 1293,960 1293,265 463,265
GND on Top Layer "Top Layer-No Net" (solid, pour order 6): 958,960 956,958 956,759 1028,759 1066,797 1066,960

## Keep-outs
Keep-Out Layer:
  text ".Layer_Name" at -837,-1631.49 h60

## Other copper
Top Layer:
  region net V+: 306.34,880.74 334.34,880.74 334.34,856.74 306.34,856.74
  region net SCL: 345.71,841.37 373.71,841.37 373.71,817.37 345.71,817.37
  region: 297.42,735.21
  region net SDA: 306.34,802 334.34,802 334.34,778 306.34,778
  region: 308.34,801
  region net GND: 976,67 976,213 776,213 776,67
  region net VCC: 729,67 729,213.12 521,213.12 521,67
  region net GND: 989.28,950.27 1055.73,950.27 1056,950 1056,857 989,857
  text "'.PRJ_Number'" at 1379.5,-1428.67 h60
  text ".Layer_Name" at -837,-1631.49 h60
Bottom Layer:
  region net VCC: 521,67 521,213.12 729,213.12 729,67
  region net GND: 776,67 776,265 976,265 976,67
  text "'.PRJ_Number'" at 1379.5,-1428.67 h60
  text ".Layer_Name" at -837,-1631.49 h60

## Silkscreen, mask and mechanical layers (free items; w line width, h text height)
Top Overlay:
  lines w6: 264.34,795 294.34,795 ; 271.34,787 288.34,787 ; 276.34,779 282.34,779 ; 279.34,795 279.34,807
  text "TIDA-01624'.SCH_Rev'" at 671,1344.35 h50
  text "BLE Temp Patch" at 673,1298.91 h50
  text "V+" at 339.34,861 h30
  text "SCL" at 379.99,820 h30
  text "SDA" at 341.99,779 h30
  text "-" at 878,248 h30 r180
  text "+" at 650.76,230 h30 r90
  text "'.PRJ_Number'" at 1379.5,-1428.67 h60
  text ".Layer_Name" at -837,-1631.49 h60
Bottom Overlay:
  lines w10: 70,630 220,630 220,920 70,920 70,630
  text "TMP117" at 192,640 h30
  text "For Demo Purposes Only.   / Not for Diagnostic or Therapeutic Use." at 1302,227 h60
  text "'.PRJ_Number'" at 1379.5,-1428.67 h60
  text ".Layer_Name" at -837,-1631.49 h60
Top Paste:
  text ".Layer_Name" at -837,-1631.49 h60
Bottom Paste:
  text ".Layer_Name" at -837,-1631.49 h60
Top Solder:
  text "'.PRJ_Number'" at 1379.5,-1428.67 h60
  text ".Layer_Name" at -837,-1631.49 h60
  text ".Layer_Name" at -837,-1631.49 h60
Bottom Solder:
  text "'.PRJ_Number'" at 1379.5,-1428.67 h60
  text ".Layer_Name" at -837,-1631.49 h60
Drill Guide:
  text ".Layer_Name" at -837,-1631.49 h60
M1 Board Outline:
  circle w10: c751,751 r750.36
  text ".Layer_Name" at -837,-1631.49 h60
M2 Board Dimensions:
  rectangle: -1289,-1173 -914,-1048
  rectangle: -1414,-1048 -1289,-923
  lines w7: -1414,-1048 -414,-1048 ; -1414,-923 -1414,-1173 -414,-1173 -414,-923 ; -1386,-923 -386,-923 ; -1289,-1173 -1289,-923 ; -1164,-1173 -1164,-923 ; -914,-1173 -914,-923 ; -664,-1173 -664,-923
  text "'.PRJ_Number'" at 1379.5,-1428.67 h60
  text ".Layer_Name" at -837,-1631.49 h60
M3 3D STEP Top:
  text ".Layer_Name" at -837,-1631.49 h60
M4 3D STEP Bottom:
  text ".Layer_Name" at -837,-1631.49 h60
M5 Assembly Top:
  lines w10: -1706,-1703.17 4894,-1703.17 ; -1706,-1499.83 4896,-1499.83 ; -1706,-1296.5 -1706,-1906.5 2299,-1906.5 4896,-1906.5 4896,-1296.5 -1705.5,-1296.5 -1705.5,-1906.5 -130,-1906.5 ; 759,-1906.5 759,-1296.5 ; 2026,-1499.83 2026,-1296.5 ; 2866,-1499.83 2866,-1296.5 ; 3488,-1913 3488,-1710.17
  text "COMPONENTS MARKED 'DNP' SHOULD NOT BE POPULATED." at -260.5,-1091.5 h60
  text "ASSEMBLY VARIANT:" at -261,-1207 h60
  text ".VariantName" at 775,-1207 h60
  text "PCB VIEWED FROM TOP SIDE" at -1642.5,-1428.67 h60
  text "BOARD #:" at 834,-1428.67 h60
  text "'.PRJ_Number'" at 1379.5,-1428.67 h60
  text "REV:" at 2224,-1428.67 h60
  text "'.SCH_Rev'" at 2515.5,-1428.67 h60
  text "SVN REV:" at 3062,-1428.67 h60
  text ".VersionControl_RevNumber" at 3568,-1428.67 h60
  text "TID #:" at 834,-1632 h60
  text "'.PRJ_Number'" at 1379.5,-1632 h60
  text "PLOT NAME =" at -1642.5,-1837.34 h60
  text ".plot_File_Name" at -837,-1837.34 h60
  text "GENERATED    :" at 836,-1837.34 h60
  text ".Print_Date" at 1705.5,-1837.34 h60
  text ".Print_Time" at 2434.5,-1837.34 h60
  text "TEXAS INSTRUMENTS" at 3699,-1837.34 h60
M9 Title Sheet:
  drawing of 57 lines, arcs and shapes, not listed
  text "1" at -674.16,7263.5 h70
  text "2" at 1821.5,7263.5 h70
  text "3" at 4310.84,7263.5 h70
  text "4" at 6817.51,7263.5 h70
  text "5" at 9316.5,7263.5 h70
  text "6" at 11821.5,7263.5 h70
  text "A" at -1830.5,6120.5 h70
  text "A" at 12969.5,6120.5 h70
  text "B" at -1830.5,3740.5 h70
  text "B" at 12969.5,3740.5 h70
  text "C" at -1830.5,1365.5 h70
  text "C" at 12969.5,1365.5 h70
  text "PROJECT TITLE:" at 9929.5,-495.5 h45
  text "'.PRJ_Title'" at 9979.5,-628.83 h70
  text "DESIGNED FOR:" at 9929.5,-796.5 h45
  text "Public" at 9979.5,-936.5 h70
  text "D" at -1830.5,-1004.5 h70
  text "D" at 12969.5,-1004.5 h70
  text "FILE NAME:" at 9929.5,-1096.5 h45
  text "'.Pcb_File_Name_No_Path'" at 9979.5,-1216.5 h70
  text "Texas Instruments (TI) and/or its licensors do not warrant the accuracy or completeness of this specification" at 4960,-1378.34 h45
  text "ENGINEER:" at 9929.5,-1386.5 h45
  text "LAYOUT BY:" at 11434.5,-1386.5 h45
  text "or any information contained therein. TI and/or its licensors do not warrant that this design will meet" at 4915.01,-1491 h45
  text "'.PRJ_Engineer'" at 9979.5,-1541.49 h70
  text "'.PRJ_Engineer'" at 11485,-1541.49 h70
  text "the specifications, will be suitable for your application or fit for any particular purpose, or will operate in" at 4915.01,-1603.67 h45
  text ".Layer_Name" at -837,-1631.49 h60
  text "ALTIUM DESIGNER VERSION:" at 11434.5,-1696.5 h45
  text "an implementation. TI and/or its licensors do not warrant that the design is production worthy. You should" at 4915.01,-1716.33 h45
  text "completely validate and test your design implementation to confirm the system functionality for your application." at 4960,-1829 h45
  text ".print_Scale" at 9979.5,-1829.83 h70
  text "17.1" at 11485,-1829.83 h70
  text "1" at -674.16,-2036.5 h70
  text "2" at 1821.5,-2036.5 h70
  text "3" at 4310.84,-2036.5 h70
  text "4" at 6817.51,-2036.5 h70
  text "5" at 9316.5,-2036.5 h70
  text "6" at 11821.5,-2036.5 h70
M10 Fab Notes:
  drawing of 189 lines, arcs and shapes, not listed
  text "DESIGN INFORMATION" at 10968.02,5583.17 h60
  text "MIN. TRACK WIDTH:" at 10323.46,5451.05 h60
  text "6" at 11419.7,5451.05 h60
  text "MIL" at 11574.46,5451.05 h60
  text "MIN. CLEARANCE:" at 10323.46,5326.92 h60
  text "0.2" at 11359.7,5326.93 h60
  text "mm" at 11574.46,5326.92 h60
  text "MIN. VIA PAD SIZE:" at 10323.46,5202.8 h60
  text "20" at 11389.71,5202.8 h60
  text "MIL" at 11574.46,5202.8 h60
  text "0.05mm (2MIL)" at 11018.46,5072.9 h60
  text "MINIMUM ANNULAR RING" at 9994.23,5064.67 h60
  text "EXTERNAL" at 11726.46,5064.67 h60
  text "PER" at 10194.23,4954.55 h60
  text "IPC-D-275 CLASS 2 LEVEL C" at 10414.23,4954.54 h60
  text "MIL, HOLES" at 11902.46,4854.07 h60
  text "+/-" at 11510,4845.48 h60
  text "+/-" at 12364,4845.48 h60
  text "REGISTRATION TOLERANCES:" at 9994.23,4844.42 h60
  text "METAL" at 11194,4844.42 h60
  text "5" at 11770.2,4844.42 h60
  text "3" at 12603.2,4844.42 h60
  text "MIL" at 12719.46,4844.42 h60
  text "HOLE SIZE TOLERANCE (UNLESS OTHERWISE SPECIFIED):" at 9994.23,4746.1 h60
  text "+/-" at 12364,4743.23 h60
  text "3" at 12603.2,4742.17 h60
  text "MIL" at 12719.46,4742.17 h60
  text "MATERIAL:" at 9919.46,4604.52 h60
  text "FR-4 High Tg" at 10905.9,4476 h60
  text "X" at 11646,4467 h60
  text "Flex (Polymide)" at 12116,4467 h60
  text "FR-408" at 10340.46,4463.49 h60
  text "OTHER" at 11828.46,4463.49 h60
  text "6.4 MIL (0.163mm) +/-10%" at 10660.56,4320.46 h60
  text "X" at 10540.46,4318.01 h60
  text "THICKNESS:" at 9994.23,4312.24 h60
  text "OTHER" at 11945.46,4312.24 h60
  text "TOLERANCE:" at 9994.23,4173.92 h60
  text "X" at 10842.46,4173.92 h60
  text "ANSI IPC-6012 TYPE 3 CLASS 2" at 11020.48,4173.92 h60
  text "OTHER +/-" at 11020.46,4029.73 h60
  text "BOW & TWIST:" at 9994.23,3884.54 h60
  text "X" at 10842.46,3884.54 h60
  text "ANSI IPC-6012 TYPE 3 CLASS 2" at 11020.48,3884.54 h60
  text "OTHER +/-" at 11020.46,3737.85 h60
  text "DRILLING:" at 9919.46,3607.23 h60
  text "NC_DRILL FILES" at 11680.46,3502.04 h60
  text "REFERENCE:" at 9994.23,3498.1 h60
  text "X" at 10651.46,3498.01 h60
  text "AS SHOWN" at 10829.46,3498.1 h60
  text "X" at 11552.46,3498.1 h60
  text "OTHER" at 11978.46,3355.85 h60
  text "PTH COPPER THICKNESS:" at 9993.91,3352.32 h60
  text "X" at 11133.14,3352.32 h60
  text "1 mil" at 11261.14,3352.32 h60
  text "BOARD FINISH:" at 9919.46,3204.73 h60
  text "SILKSCREEN:" at 10074.68,3094.6 h60
  text "X" at 11032.46,3094.6 h60
  text "TOP" at 11149.46,3094.6 h60
  text "X" at 11542.46,3094.6 h60
  text "BOTTOM" at 11660.46,3094.6 h60
  text "SILKSCREEN COLOR:" at 10074.68,2939.41 h60
  text "X" at 11031.46,2939.41 h60
  text "WHITE" at 11149.46,2939.41 h60
  text "OTHER" at 11660.46,2939.41 h60
  text "GREEN" at 11280.46,2795.96 h60
  text "OTHER" at 11898.46,2795.96 h60
  text "X" at 11745,2795 h60
  text "SOLDER RESIST COLOR:" at 10074.68,2789.1 h60
  text "N/A" at 12436.83,2788.44 h60
  text "X" at 11162.46,2641.71 h60
  text "MATTE" at 11280.46,2641.71 h60
  text "SEMI-GLOSS" at 11898,2641.07 h60
  text "IMMERSION GOLD (ENIG)" at 10980.46,2468.94 h60
  text "ENEPIG" at 12318,2461.72 h60
  text "SURFACE FINISH:" at 9919.46,2460.72 h60
  text "X" at 10802.46,2460.72 h60
  text "IMM. TIN/SILVER OR EQUIV" at 10249,2323.4 h60
  text "OTHER" at 11680.46,2319.47 h60
  text "ARRAY/PANEL:" at 9919.46,2164.09 h60
  text "CUT AND TRIM PER M1 BOARD OUTLINE" at 10980.46,2155.87 h60
  text "N.C. ROUTE" at 10980.46,2019.9 h60
  text "X" at 11668.46,2019.9 h60
  text "V. SCORE" at 11846.46,2019.9 h60
  text "CERTIFICATION:" at 9919.46,1890.77 h60
  text "MATERIALS AND WORKMANSHIP FOR ALL PCBS" at 10644.46,1890.77 h60
  text "TO MEET OR EXCEED THE REQUIREMENTS OF:" at 10644.46,1796.71 h60
  text "X" at 10281.97,1668.08 h60
  text "ANSI IPC-A-600F CLASS ->" at 10409.96,1668.08 h60
  text "X" at 12057.97,1668.08 h60
  text "2" at 12167.96,1668.08 h60
  text "1" at 11852.96,1666.58 h60
  text "3" at 12521.96,1666.58 h60
  text "X" at 11093.97,1520.39 h60
  text "RoHS" at 11221.96,1520.39 h60
  text "OTHER" at 11866.36,1520.39 h60
  text "PER ORDER" at 12263.42,1520.39 h60
  text "ALL BOARDS MUST MEET OR EXCEED UL94-V0 REQUIREMENTS." at 9947,1366.57 h60
  text "PCB MUST BEAR THE UL94V-0 UL REGISTERED MATERIAL ID NUMBER" at 9947,1250.5 h60
  text "ADDITIONAL REQUIREMENTS:" at 9919.46,1081.08 h60
  text "MICROSECTION:" at 9994.23,973.95 h60
  text "YES" at 10899.96,973.95 h60
  text "REQUIRED" at 11761.46,829.62 h60
  text "BARE BOARD ELEC. TEST:" at 9994.23,826.76 h60
  text "NONE" at 11299.96,826.76 h60
  text "X" at 11643.46,826.76 h60
  text "PER ORDER" at 12353.46,826.76 h60
  text "XX MIL VIAS REQUIRE NON-CONDUCTIVE FILL AND PLANARIZE" at 10162.38,621.82 h59
  text "XX MIL VIAS REQUIRE CONDUCTIVE FILL AND PLANARIZE" at 10170.38,517.84 h60
  text "OUTER XX MIL TRACES REQUIRE 50 OHM SINGLE-ENDED IMPEDANCE" at 10169.39,354.46 h58
  text "LAYER 2 & 3 (INNER LAYERS) XX MIL WIDE, XX MIL SPACE / TRACES REQUIRE 100 OHM DIFFERENTIAL IMPEDANCE" at 10161.39,118.74 h60
  text ".Layer_Name" at -837,-1631.49 h60
M11 Gerber Information:
  lines w10: -1706,-1703.17 4894,-1703.17 ; -1706,-1499.83 4896,-1499.83 ; -1706,-1296.5 -1706,-1906.5 2299,-1906.5 4896,-1906.5 4896,-1296.5 -1705.5,-1296.5 -1705.5,-1906.5 -130,-1906.5 ; 759,-1906.5 759,-1296.5 ; 2026,-1499.83 2026,-1296.5 ; 2866,-1499.83 2866,-1296.5 ; 3488,-1913 3488,-1710.17
  text "BOARD #:" at 834,-1428.67 h60
  text "REV:" at 2224,-1428.67 h60
  text "SVN REV:" at 3062,-1428.67 h60
  text ".VersionControl_RevNumber" at 3568,-1428.67 h60
  text "LAYER NAME =" at -1642.5,-1631.49 h60
  text "TID #:" at 834,-1632 h60
  text "PLOT NAME =" at -1642.5,-1837.34 h60
  text ".plot_File_Name" at -837,-1837.34 h60
  text "GENERATED    :" at 836,-1837.34 h60
  text ".Print_Date" at 1705.5,-1837.34 h60
  text ".Print_Time" at 2434.5,-1837.34 h60
  text "TEXAS INSTRUMENTS" at 3699,-1837.34 h60
M12 Stackup:
  drawing of 232 lines, arcs and shapes, not listed
  text "Layer" at 3926.34,1263 h60
  text "Name" at 4336.26,1263 h60
  text "Material" at 5266,1263 h60
  text "Thickness" at 5895.84,1263 h60
  text "Constant" at 6545.68,1263 h60
  text "Stiffened" at 7115.54,1263 h60
  text "Flex" at 7735.38,1263 h60
  text "1" at 3926.34,1143 h60
  text "Top Overlay" at 4336.26,1143 h60
  text "2" at 3926.34,1023 h60
  text "Top Solder" at 4336.26,1023 h60
  text "Polymide" at 5266,1023 h60
  text "1.00mil" at 5895.84,1023 h60
  text "3.3" at 6545.68,1023 h60
  text "3" at 3926.34,903 h60
  text "Top Layer" at 4336.26,903 h60
  text "Copper" at 5266,903 h60
  text "0.70mil" at 5895.84,903 h60
  text "4" at 3926.34,783 h60
  text "Stiffener" at 4336.26,783 h60
  text "Polyimide" at 5266,783 h60
  text "5.00mil" at 5895.84,783 h60
  text "4.2" at 6545.68,783 h60
  text "5" at 3926.34,663 h60
  text "Flex Substrate" at 4336.26,663 h60
  text "Polymide" at 5266,663 h60
  text "3.00mil" at 5895.84,663 h60
  text "3.3" at 6545.68,663 h60
  text "6" at 3926.34,543 h60
  text "Bottom Layer" at 4336.26,543 h60
  text "Copper" at 5266,543 h60
  text "0.70mil" at 5895.84,543 h60
  text "7" at 3926.34,423 h60
  text "Bottom Solder" at 4336.26,423 h60
  text "Polyimide" at 5266,423 h60
  text "1.00mil" at 5895.84,423 h60
  text "3.3" at 6545.68,423 h60
  text "8" at 3926.34,303 h60
  text "Bottom Overlay" at 4336.26,303 h60
  text ".Layer_Name" at -837,-1631.49 h60
M13 Component Bodies Top:
  text ".Layer_Name" at -837,-1631.49 h60
M14 Component Bodies Bottom:
  text ".Layer_Name" at -837,-1631.49 h60
M15 Courtyards Top:
  text ".Layer_Name" at -837,-1631.49 h60
M16 Courtyards Bottom:
  text ".Layer_Name" at -837,-1631.49 h60
Drill Drawing:
  lines w10: 3922.09,2212.7 3949.72,2226.51 3977.34,2212.7 3963.53,2240.32 3977.34,2267.95 3949.72,2254.14 3922.09,2267.95 3935.9,2240.32 3922.09,2212.7 ; 3922.09,2392.27 3977.34,2392.27 3949.72,2337.02 3922.09,2392.27 ; 3922.09,2461.34 3977.34,2461.34 3977.34,2516.59 3922.09,2516.59 3922.09,2461.34 ; 3922.09,2599.47 3935.9,2599.47 3949.72,2585.66 3963.53,2599.47 3977.34,2599.47 3963.53,2613.28 3977.34,2627.1 3963.53,2627.1 3949.72,2640.91 3935.9,2627.1 3922.09,2627.1 3935.9,2613.28 3922.09,2599.47
  lines w12: 3872,2175.4 7103.49,2175.4 ; 3872,2672.68 7103.49,2672.68 ; 4209.86,2051.08 4209.86,2797 ; 4541.86,2051.08 4541.86,2797 ; 5178.43,2051.08 5178.43,2797 ; 5437.57,2051.08 5437.57,2797 ; 5812.72,2051.08 5812.72,2797 ; 6537.05,2051.08 6537.05,2797 ; 3872,2051.08 7103.49,2051.08 7103.49,2797 3872,2797 3872,2051.08
  text "Symbol" at 3946.59,2709.98 h72
  text "Quantity" at 4247.16,2709.98 h72
  text "Finished Hole Size" at 4579.16,2709.98 h72
  text "Plated" at 5215.72,2709.98 h72
  text "Hole Type" at 5474.86,2709.98 h72
  text "Drill Layer Pair" at 5850.02,2709.98 h72
  text "Hole Tolerance" at 6574.35,2709.98 h72
  text "3" at 4247.16,2585.66 h60
  text "39.00mil (0.991mm)" at 4579.16,2585.66 h60
  text "NPTH" at 5215.72,2585.66 h60
  text "Round" at 5474.86,2585.66 h60
  text "Top Layer - Bottom Layer" at 5850.02,2585.66 h60
  text "3" at 4247.16,2461.34 h60
  text "10.00mil (0.254mm)" at 4579.16,2461.34 h60
  text "PTH" at 5215.72,2461.34 h60
  text "Round" at 5474.86,2461.34 h60
  text "Top Layer - Bottom Layer" at 5850.02,2461.34 h60
  text "31" at 4247.16,2337.02 h60
  text "12.00mil (0.305mm)" at 4579.16,2337.02 h60
  text "PTH" at 5215.72,2337.02 h60
  text "Round" at 5474.86,2337.02 h60
  text "Top Layer - Bottom Layer" at 5850.02,2337.02 h60
  text "2" at 4247.16,2212.7 h60
  text "40.00mil (1.016mm)" at 4579.16,2212.7 h60
  text "PTH" at 5215.72,2212.7 h60
  text "Round" at 5474.86,2212.7 h60
  text "Top Layer - Bottom Layer" at 5850.02,2212.7 h60
  text "39 Total" at 4247.16,2088.38 h60
  text "'.PRJ_Number'" at 1379.5,-1428.67 h60
  text ".Layer_Name" at -837,-1631.49 h60
Mechanical 17:
  text ".Layer_Name" at -837,-1631.49 h60
Mechanical 18:
  text ".Layer_Name" at -837,-1631.49 h60
Mechanical 19:
  text ".Layer_Name" at -837,-1631.49 h60

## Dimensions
-1414,-1173 to -414,-1173 on M2 Board Dimensions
